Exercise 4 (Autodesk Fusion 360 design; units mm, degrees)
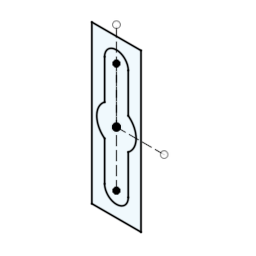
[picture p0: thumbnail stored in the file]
sketch "Sketch1" plane through (0, 0, 0) normal (0, 1, 0) x axis (1, 0, 0)
  line L1 (12.5, -40) -> (-12.5, -40)
  line L2 (12.5, 40) -> (12.5, -40)
  line L3 (-12.5, 40) -> (12.5, 40)
  line L4 (-12.5, -40) -> (-12.5, 40)
  line L5 (0, 0) -> (24.2686, 0)
  line L6 (0, -45.0922) -> (0, 0)
  line L7 (0, -28) -> (0, 28)
  line L8 (-6, 8) -> (-6, 28)
  line L9 (-6, -28) -> (-6, -8)
  line L10 (6, -8) -> (6, -28)
  line L11 (6, 28) -> (6, 8)
  arc A1 centre (0, -28) radius 6 clockwise from (6, -28) to (-6, -28)
  arc A2 centre (0, 28) radius 6 clockwise from (-6, 28) to (6, 28)
  arc A3 centre (0, 0) radius 10 clockwise from (6, 8) to (6, -8)
  arc A4 centre (0, 0) radius 10 clockwise from (-6, -8) to (-6, 8)
  point P1 (0, 0)
  point P7 (0, 0)
  point P15 (0, 0)
  point P16 (0, 0)
  point P17 (-6, -8)
  point P19 (6, 8)
  point P2 (-12.5, -40)
  point P5 (-12.5, 40)
  point P13 (0, 28)
  point P14 (0, -28)
  point P4 (12.5, 40)
  horizontal L1
  vertical L2
  horizontal L3
  vertical L4
  coincident P1 P7
  perpendicular L2 L5
  perpendicular L5 L6
  symmetric L1 L3 L5
  symmetric L2 L4 L6
  tangent A1 L8
  tangent A1 L10
  parallel L8 L10
  tangent A2 L10
  tangent A2 L8
  perpendicular L5 L7
  coincident P1 P15
  midpoint L7 P15
  coincident P1 P16
  coincident P17 L8
  coincident P19 L10
  concentric A3 A4
  collinear L8 L9
  collinear L10 L11
  equal A3 A4
  dimension "d1" distance P2 P5 = 80
  dimension "d3" radius A1 = 6
  dimension "d4" distance P13 P14 = 56
  dimension "d5" radius A3 = 10
  dimension "d6" distance P4 P5 = 25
